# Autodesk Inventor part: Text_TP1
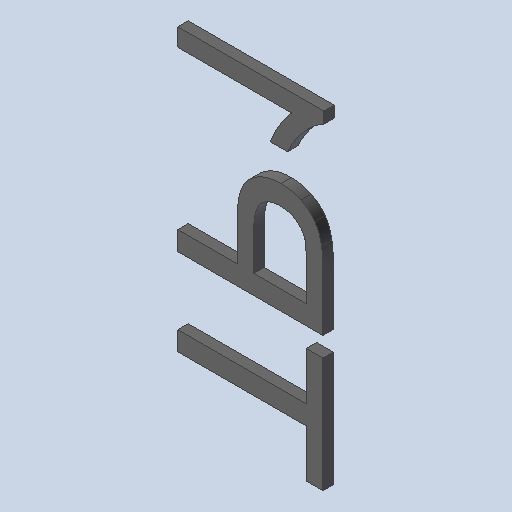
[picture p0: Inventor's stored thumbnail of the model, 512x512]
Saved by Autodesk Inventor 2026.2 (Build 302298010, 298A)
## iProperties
Created: 2026-10
Part Number: Text_TP1
Material: Générique
Document SubType Name: Modeling
Designer: mel
Density: 1 g/cm^3
Appearance: Par défaut
Author: mel
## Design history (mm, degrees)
feature "Base1"
feature "Base2"
feature "Base3"
node "Solide1"
node "Solide2"
node "Solide3"
